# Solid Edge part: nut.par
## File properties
Author: Sarvanan
Template: sync ansi part.par
Last saved by: TIET
Revision: 9
Application: Solid Edge
Accuracy: 0.990
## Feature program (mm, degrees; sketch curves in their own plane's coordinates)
sketch for "Hole_1" plane through (27.3343, 36.5222, 2.54) normal (0, 0, 1) x-axis (1, 0, 0)
  hole centre (-0.0483, 0.0372) bore radius 3.302
hole "Hole_1" diameter 6.604 through
pattern "unnamed Pattern 1" of "Hole_1"
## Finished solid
Body 1: solid body, 11 faces, 22 edges, 12 vertices.
  Faces by surface: plane 8, cone 2, cylinder 1
  Edges by curve: intersection 12, line 6, circle 4
Bounding box of the edges (mm): 10.265 x 8.890 x 5.080, from (22.2017, 32.1144, -2.54) to (32.467, 41.0044, 2.54).
Cylindrical faces by radius (mm): R3.302 x1
Conical faces (half-angle, radius in mm at the cone's reference point): 45 deg R5.1326 x2
Planar faces by outward normal: +y 1, +z 1, -y 1, -z 1, oblique 4
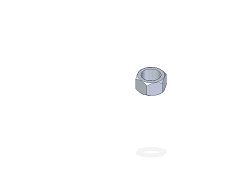
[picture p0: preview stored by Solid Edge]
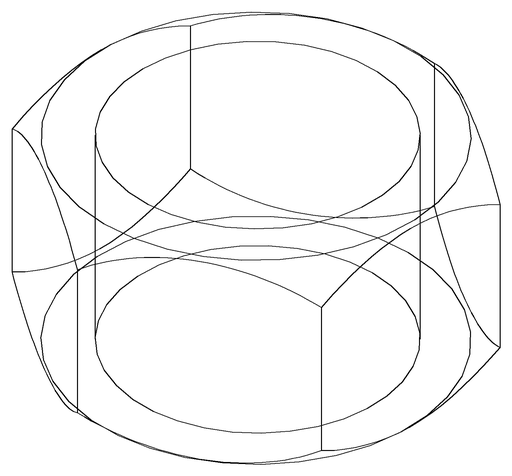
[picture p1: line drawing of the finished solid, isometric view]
